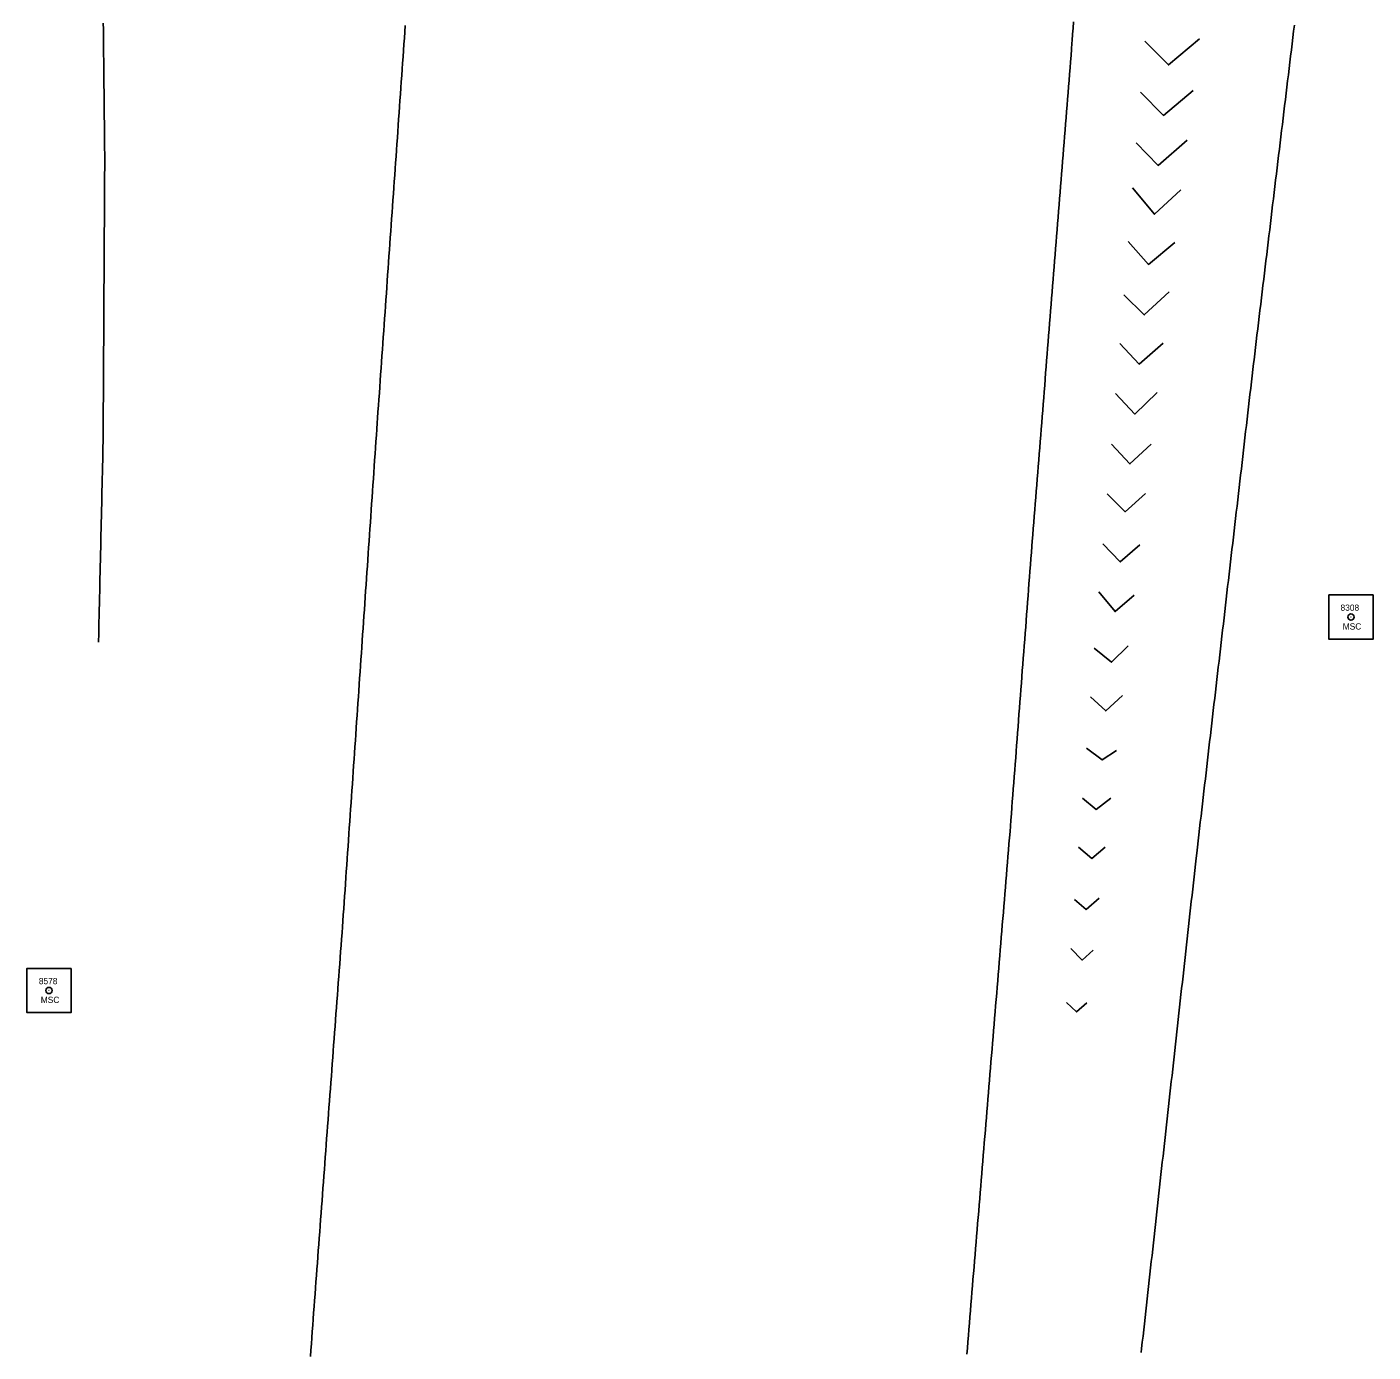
# Model space of a CAD drawing. Extents: x 205929 to 2357175, y -1785700 to 846739.
# Drawn here: x 2023502.7 to 2023718.1, y 811186.8 to 811398.9 of the extents above; entities that cross this region are included whole.
import ezdxf

# ---------------------------------------------------------------- set-up
doc = ezdxf.new("R2010")
doc.units = 0
for name, color, linetype in [('RD_HC_Survey', 7, 'Continuous'), ('RD_HC_txCode', 7, 'Continuous'), ('RD_Sketch1', 7, 'Continuous'), ('RD_SMD_Locator', 7, 'Continuous')]:
    doc.layers.add(name, color=color, linetype=linetype)

msp = doc.modelspace()

# ---------------------------------------------------------------- linework, layer by layer
at = {"layer": 'RD_HC_Survey'}
for points in [[(2023718.06, 811307.98), (2023710.99, 811307.98), (2023710.99, 811300.91), (2023718.06, 811300.91)], [(2023509.78, 811248.22), (2023502.71, 811248.22), (2023502.71, 811241.15), (2023509.78, 811241.15)]]:
    msp.add_lwpolyline(points, close=True, dxfattribs=at)
for centre in [(2023714.53, 811304.45), (2023506.25, 811244.69)]:
    msp.add_circle(centre, 0.5, dxfattribs=at)
at = {"layer": 'RD_Sketch1'}
for points in [[(2023514.93, 811399.5), (2023514.94, 811398.5), (2023514.95, 811397.5), (2023514.96, 811396.5), (2023514.97, 811395.5), (2023514.98, 811394.5), (2023514.99, 811393.5), (2023515, 811392.5), (2023515.01, 811391.5), (2023515.03, 811390.5), (2023515.04, 811389.5), (2023515.05, 811388.5), (2023515.06, 811387.5), (2023515.07, 811386.5), (2023515.08, 811385.5), (2023515.09, 811384.5), (2023515.1, 811383.5), (2023515.11, 811382.5), (2023515.12, 811381.5), (2023515.13, 811380.5), (2023515.14, 811379.5), (2023515.16, 811378.51), (2023515.16, 811378.29), (2023515.15, 811377.29), (2023515.15, 811376.29), (2023515.14, 811375.29), (2023515.14, 811374.29), (2023515.13, 811373.29), (2023515.12, 811372.29), (2023515.12, 811371.3), (2023515.11, 811370.3), (2023515.11, 811369.3), (2023515.1, 811368.3), (2023515.1, 811367.3), (2023515.09, 811366.3), (2023515.08, 811365.3), (2023515.08, 811364.3), (2023515.07, 811363.3), (2023515.07, 811362.3), (2023515.06, 811361.3), (2023515.06, 811360.3), (2023515.05, 811359.3), (2023515.05, 811358.3), (2023515.04, 811357.3), (2023515.03, 811356.3), (2023515.03, 811355.31), (2023515.02, 811354.31), (2023515.02, 811353.31), (2023515.01, 811352.31), (2023515.01, 811351.31), (2023515, 811350.31), (2023514.99, 811349.31), (2023514.99, 811348.31), (2023514.98, 811347.31), (2023514.98, 811346.31), (2023514.97, 811345.31), (2023514.97, 811344.31), (2023514.96, 811343.31), (2023514.96, 811342.31), (2023514.95, 811341.31), (2023514.94, 811340.31), (2023514.94, 811339.32), (2023514.93, 811338.32), (2023514.93, 811337.32), (2023514.92, 811336.32), (2023514.92, 811335.32), (2023514.91, 811334.32), (2023514.9, 811333.32), (2023514.9, 811332.59), (2023514.88, 811331.59), (2023514.85, 811330.59), (2023514.83, 811329.6), (2023514.81, 811328.6), (2023514.79, 811327.6), (2023514.76, 811326.6), (2023514.74, 811325.6), (2023514.72, 811324.6), (2023514.69, 811323.6), (2023514.67, 811322.6), (2023514.65, 811321.6), (2023514.62, 811320.6), (2023514.6, 811319.6), (2023514.58, 811318.6), (2023514.56, 811317.6), (2023514.53, 811316.6), (2023514.51, 811315.61), (2023514.49, 811314.61), (2023514.46, 811313.61), (2023514.44, 811312.61), (2023514.42, 811311.61), (2023514.39, 811310.61), (2023514.37, 811309.61), (2023514.35, 811308.61), (2023514.33, 811307.61), (2023514.3, 811306.61), (2023514.28, 811305.61), (2023514.26, 811304.61), (2023514.23, 811303.61), (2023514.21, 811302.61), (2023514.19, 811301.62), (2023514.16, 811300.62), (2023514.16, 811300.44)], [(2023563.24, 811399.1), (2023563.17, 811398.1), (2023563.1, 811397.1), (2023563.03, 811396.11), (2023562.96, 811395.11), (2023562.89, 811394.11), (2023562.81, 811393.11), (2023562.74, 811392.12), (2023562.67, 811391.12), (2023562.6, 811390.12), (2023562.53, 811389.13), (2023562.46, 811388.13), (2023562.39, 811387.13), (2023562.32, 811386.14), (2023562.25, 811385.14), (2023562.18, 811384.14), (2023562.11, 811383.14), (2023562.04, 811382.15), (2023561.97, 811381.15), (2023561.9, 811380.15), (2023561.83, 811379.16), (2023561.76, 811378.16), (2023561.69, 811377.16), (2023561.62, 811376.16), (2023561.55, 811375.17), (2023561.48, 811374.17), (2023561.41, 811373.17), (2023561.34, 811372.18), (2023561.27, 811371.18), (2023561.2, 811370.18), (2023561.13, 811369.18), (2023561.06, 811368.19), (2023560.99, 811367.19), (2023560.91, 811366.19), (2023560.84, 811365.2), (2023560.77, 811364.2), (2023560.7, 811363.2), (2023560.63, 811362.21), (2023560.56, 811361.21), (2023560.49, 811360.21), (2023560.42, 811359.21), (2023560.35, 811358.22), (2023560.28, 811357.22), (2023560.21, 811356.22), (2023560.14, 811355.23), (2023560.07, 811354.23), (2023560, 811353.23), (2023559.93, 811352.23), (2023559.86, 811351.24), (2023559.79, 811350.24), (2023559.72, 811349.24), (2023559.65, 811348.25), (2023559.58, 811347.25), (2023559.51, 811346.25), (2023559.44, 811345.25), (2023559.37, 811344.26), (2023559.3, 811343.26), (2023559.23, 811342.26), (2023559.16, 811341.27), (2023559.09, 811340.27), (2023559.01, 811339.27), (2023558.94, 811338.28), (2023558.87, 811337.28), (2023558.8, 811336.28), (2023558.75, 811335.54), (2023558.68, 811334.54), (2023558.61, 811333.55), (2023558.55, 811332.55), (2023558.48, 811331.55), (2023558.41, 811330.55), (2023558.34, 811329.56), (2023558.27, 811328.56), (2023558.2, 811327.56), (2023558.13, 811326.57), (2023558.06, 811325.57), (2023558, 811324.57), (2023557.93, 811323.58), (2023557.86, 811322.58), (2023557.79, 811321.58), (2023557.72, 811320.58), (2023557.65, 811319.59), (2023557.58, 811318.59), (2023557.51, 811317.59), (2023557.45, 811316.6), (2023557.38, 811315.6), (2023557.31, 811314.6), (2023557.24, 811313.6), (2023557.17, 811312.61), (2023557.1, 811311.61), (2023557.03, 811310.61), (2023556.96, 811309.62), (2023556.9, 811308.62), (2023556.83, 811307.62), (2023556.76, 811306.62), (2023556.69, 811305.63), (2023556.62, 811304.63), (2023556.55, 811303.63), (2023556.48, 811302.64), (2023556.41, 811301.64), (2023556.35, 811300.64), (2023556.28, 811299.64), (2023556.21, 811298.65), (2023556.14, 811297.65), (2023556.07, 811296.65), (2023556, 811295.66), (2023555.93, 811294.66), (2023555.86, 811293.66), (2023555.8, 811292.66), (2023555.73, 811291.67), (2023555.66, 811290.67), (2023555.59, 811289.67), (2023555.52, 811288.68), (2023555.45, 811287.68), (2023555.38, 811286.68), (2023555.32, 811285.68), (2023555.25, 811284.69), (2023555.18, 811283.69), (2023555.11, 811282.69), (2023555.04, 811281.7), (2023554.97, 811280.7), (2023554.9, 811279.7), (2023554.83, 811278.7), (2023554.77, 811277.71), (2023554.7, 811276.71), (2023554.63, 811275.71), (2023554.56, 811274.72), (2023554.49, 811273.72), (2023554.42, 811272.72), (2023554.35, 811271.72), (2023554.28, 811270.73), (2023554.22, 811269.73), (2023554.15, 811268.73), (2023554.08, 811267.74), (2023554.01, 811266.74), (2023553.94, 811265.74), (2023553.87, 811264.74), (2023553.8, 811263.75), (2023553.73, 811262.75), (2023553.67, 811261.75), (2023553.6, 811260.76), (2023553.53, 811259.76), (2023553.46, 811258.76), (2023553.39, 811257.76), (2023553.32, 811256.77), (2023553.25, 811255.77), (2023553.19, 811254.89), (2023553.12, 811253.89), (2023553.04, 811252.9), (2023552.97, 811251.9), (2023552.89, 811250.9), (2023552.82, 811249.91), (2023552.75, 811248.91), (2023552.67, 811247.91), (2023552.6, 811246.92), (2023552.52, 811245.92), (2023552.45, 811244.92), (2023552.37, 811243.93), (2023552.3, 811242.93), (2023552.23, 811241.93), (2023552.15, 811240.94), (2023552.08, 811239.94), (2023552, 811238.94), (2023551.93, 811237.95), (2023551.85, 811236.95), (2023551.78, 811235.95), (2023551.7, 811234.95), (2023551.63, 811233.96), (2023551.56, 811232.96), (2023551.48, 811231.96), (2023551.41, 811230.97), (2023551.33, 811229.97), (2023551.26, 811228.97), (2023551.18, 811227.98), (2023551.11, 811226.98), (2023551.03, 811225.98), (2023550.96, 811224.99), (2023550.89, 811223.99), (2023550.81, 811222.99), (2023550.74, 811222), (2023550.66, 811221), (2023550.59, 811220), (2023550.51, 811219.01), (2023550.44, 811218.01), (2023550.36, 811217.01), (2023550.29, 811216.02), (2023550.22, 811215.02), (2023550.14, 811214.02), (2023550.07, 811213.03), (2023549.99, 811212.03), (2023549.92, 811211.03), (2023549.84, 811210.04), (2023549.77, 811209.04), (2023549.7, 811208.04), (2023549.62, 811207.04), (2023549.55, 811206.05), (2023549.47, 811205.05), (2023549.4, 811204.05), (2023549.32, 811203.06), (2023549.25, 811202.06), (2023549.17, 811201.06), (2023549.1, 811200.07), (2023549.03, 811199.07), (2023548.95, 811198.07), (2023548.88, 811197.08), (2023548.8, 811196.08), (2023548.73, 811195.08), (2023548.65, 811194.09), (2023548.58, 811193.09), (2023548.5, 811192.09), (2023548.43, 811191.1), (2023548.36, 811190.1), (2023548.28, 811189.1), (2023548.21, 811188.11), (2023548.13, 811187.11), (2023548.06, 811186.11)], [(2023670.16, 811399.7), (2023670.08, 811398.7), (2023670, 811397.71), (2023669.92, 811396.71), (2023669.89, 811396.32), (2023669.82, 811395.32), (2023669.74, 811394.33), (2023669.66, 811393.33), (2023669.58, 811392.33), (2023669.5, 811391.34), (2023669.42, 811390.34), (2023669.34, 811389.34), (2023669.26, 811388.35), (2023669.18, 811387.35), (2023669.1, 811386.35), (2023669.02, 811385.36), (2023668.94, 811384.36), (2023668.86, 811383.37), (2023668.78, 811382.37), (2023668.7, 811381.37), (2023668.62, 811380.38), (2023668.54, 811379.38), (2023668.46, 811378.38), (2023668.39, 811377.39), (2023668.31, 811376.39), (2023668.23, 811375.39), (2023668.15, 811374.4), (2023668.07, 811373.4), (2023667.99, 811372.41), (2023667.91, 811371.41), (2023667.83, 811370.41), (2023667.75, 811369.42), (2023667.67, 811368.42), (2023667.59, 811367.42), (2023667.51, 811366.43), (2023667.43, 811365.43), (2023667.35, 811364.43), (2023667.27, 811363.44), (2023667.19, 811362.44), (2023667.11, 811361.45), (2023667.04, 811360.45), (2023666.96, 811359.45), (2023666.88, 811358.46), (2023666.8, 811357.46), (2023666.72, 811356.46), (2023666.64, 811355.47), (2023666.56, 811354.47), (2023666.48, 811353.47), (2023666.4, 811352.48), (2023666.32, 811351.48), (2023666.24, 811350.49), (2023666.16, 811349.49), (2023666.08, 811348.49), (2023666, 811347.5), (2023665.92, 811346.5), (2023665.84, 811345.5), (2023665.76, 811344.51), (2023665.68, 811343.51), (2023665.61, 811342.51), (2023665.53, 811341.52), (2023665.45, 811340.52), (2023665.37, 811339.53), (2023665.29, 811338.53), (2023665.21, 811337.53), (2023665.13, 811336.54), (2023665.05, 811335.54), (2023664.97, 811334.54), (2023664.89, 811333.55), (2023664.81, 811332.55), (2023664.73, 811331.55), (2023664.65, 811330.56), (2023664.57, 811329.56), (2023664.49, 811328.57), (2023664.41, 811327.57), (2023664.33, 811326.57), (2023664.26, 811325.58), (2023664.18, 811324.58), (2023664.1, 811323.58), (2023664.02, 811322.59), (2023663.94, 811321.59), (2023663.86, 811320.59), (2023663.78, 811319.6), (2023663.7, 811318.6), (2023663.62, 811317.61), (2023663.54, 811316.61), (2023663.48, 811315.8), (2023663.4, 811314.8), (2023663.32, 811313.81), (2023663.25, 811312.81), (2023663.17, 811311.81), (2023663.1, 811310.82), (2023663.02, 811309.82), (2023662.94, 811308.82), (2023662.87, 811307.83), (2023662.79, 811306.83), (2023662.71, 811305.84), (2023662.64, 811304.84), (2023662.56, 811303.84), (2023662.49, 811302.85), (2023662.41, 811301.85), (2023662.33, 811300.85), (2023662.26, 811299.86), (2023662.18, 811298.86), (2023662.11, 811297.86), (2023662.03, 811296.87), (2023661.95, 811295.87), (2023661.88, 811294.87), (2023661.8, 811293.88), (2023661.73, 811292.88), (2023661.65, 811291.88), (2023661.57, 811290.89), (2023661.5, 811289.89), (2023661.42, 811288.89), (2023661.34, 811287.9), (2023661.27, 811286.9), (2023661.19, 811285.9), (2023661.12, 811284.91), (2023661.04, 811283.91), (2023660.96, 811282.92), (2023660.89, 811281.92), (2023660.81, 811280.92), (2023660.74, 811279.93), (2023660.66, 811278.93), (2023660.58, 811277.93), (2023660.51, 811276.94), (2023660.43, 811275.94), (2023660.35, 811274.94), (2023660.28, 811273.95), (2023660.2, 811272.95), (2023660.13, 811271.95), (2023660.05, 811270.96), (2023659.99, 811270.14), (2023659.91, 811269.14), (2023659.82, 811268.15), (2023659.74, 811267.15), (2023659.66, 811266.15), (2023659.58, 811265.16), (2023659.49, 811264.16), (2023659.41, 811263.16), (2023659.33, 811262.17), (2023659.25, 811261.17), (2023659.17, 811260.18), (2023659.08, 811259.18), (2023659, 811258.18), (2023658.92, 811257.19), (2023658.84, 811256.19), (2023658.75, 811255.2), (2023658.67, 811254.2), (2023658.59, 811253.2), (2023658.51, 811252.21), (2023658.42, 811251.21), (2023658.34, 811250.21), (2023658.26, 811249.22), (2023658.18, 811248.22), (2023658.1, 811247.23), (2023658.01, 811246.23), (2023657.93, 811245.23), (2023657.85, 811244.24), (2023657.77, 811243.24), (2023657.68, 811242.25), (2023657.6, 811241.25), (2023657.52, 811240.25), (2023657.44, 811239.26), (2023657.35, 811238.26), (2023657.27, 811237.26), (2023657.19, 811236.27), (2023657.11, 811235.27), (2023657.03, 811234.28), (2023656.94, 811233.28), (2023656.86, 811232.28), (2023656.78, 811231.29), (2023656.7, 811230.29), (2023656.61, 811229.3), (2023656.53, 811228.3), (2023656.45, 811227.3), (2023656.37, 811226.31), (2023656.28, 811225.31), (2023656.2, 811224.31), (2023656.12, 811223.32), (2023656.04, 811222.32), (2023655.96, 811221.33), (2023655.87, 811220.33), (2023655.79, 811219.33), (2023655.71, 811218.34), (2023655.63, 811217.34), (2023655.54, 811216.35), (2023655.46, 811215.35), (2023655.38, 811214.35), (2023655.3, 811213.36), (2023655.22, 811212.36), (2023655.13, 811211.36), (2023655.05, 811210.37), (2023654.97, 811209.37), (2023654.89, 811208.38), (2023654.8, 811207.38), (2023654.72, 811206.38), (2023654.64, 811205.39), (2023654.56, 811204.39), (2023654.47, 811203.39), (2023654.39, 811202.4), (2023654.31, 811201.4), (2023654.23, 811200.41), (2023654.15, 811199.41), (2023654.06, 811198.41), (2023653.98, 811197.42), (2023653.9, 811196.42), (2023653.82, 811195.43), (2023653.73, 811194.43), (2023653.65, 811193.43), (2023653.57, 811192.44), (2023653.49, 811191.44), (2023653.4, 811190.44), (2023653.32, 811189.45), (2023653.24, 811188.45), (2023653.16, 811187.46), (2023653.08, 811186.46)], [(2023705.47, 811399.18), (2023705.35, 811398.19), (2023705.23, 811397.2), (2023705.11, 811396.21), (2023704.99, 811395.21), (2023704.87, 811394.22), (2023704.75, 811393.23), (2023704.63, 811392.24), (2023704.51, 811391.24), (2023704.39, 811390.25), (2023704.27, 811389.26), (2023704.15, 811388.27), (2023704.04, 811387.27), (2023703.92, 811386.28), (2023703.8, 811385.29), (2023703.68, 811384.3), (2023703.56, 811383.3), (2023703.44, 811382.31), (2023703.32, 811381.32), (2023703.2, 811380.33), (2023703.08, 811379.34), (2023702.96, 811378.34), (2023702.84, 811377.35), (2023702.72, 811376.36), (2023702.6, 811375.37), (2023702.48, 811374.37), (2023702.36, 811373.38), (2023702.24, 811372.39), (2023702.12, 811371.4), (2023702, 811370.4), (2023701.88, 811369.41), (2023701.76, 811368.42), (2023701.64, 811367.43), (2023701.53, 811366.43), (2023701.41, 811365.44), (2023701.29, 811364.45), (2023701.17, 811363.46), (2023701.05, 811362.47), (2023700.93, 811361.47), (2023700.81, 811360.48), (2023700.69, 811359.49), (2023700.57, 811358.5), (2023700.45, 811357.5), (2023700.33, 811356.51), (2023700.21, 811355.52), (2023700.09, 811354.53), (2023699.97, 811353.53), (2023699.85, 811352.54), (2023699.73, 811351.55), (2023699.61, 811350.56), (2023699.49, 811349.57), (2023699.37, 811348.57), (2023699.25, 811347.58), (2023699.13, 811346.59), (2023699.02, 811345.6), (2023698.95, 811345.05), (2023698.83, 811344.05), (2023698.72, 811343.06), (2023698.6, 811342.07), (2023698.49, 811341.08), (2023698.37, 811340.08), (2023698.26, 811339.09), (2023698.14, 811338.1), (2023698.03, 811337.11), (2023697.91, 811336.11), (2023697.8, 811335.12), (2023697.68, 811334.13), (2023697.57, 811333.14), (2023697.45, 811332.14), (2023697.34, 811331.15), (2023697.22, 811330.16), (2023697.11, 811329.17), (2023696.99, 811328.17), (2023696.87, 811327.18), (2023696.76, 811326.19), (2023696.64, 811325.2), (2023696.53, 811324.2), (2023696.41, 811323.21), (2023696.3, 811322.22), (2023696.18, 811321.23), (2023696.07, 811320.23), (2023695.95, 811319.24), (2023695.84, 811318.25), (2023695.72, 811317.26), (2023695.61, 811316.26), (2023695.49, 811315.27), (2023695.38, 811314.28), (2023695.26, 811313.29), (2023695.15, 811312.29), (2023695.03, 811311.3), (2023694.92, 811310.31), (2023694.8, 811309.32), (2023694.69, 811308.32), (2023694.57, 811307.33), (2023694.45, 811306.34), (2023694.34, 811305.35), (2023694.22, 811304.35), (2023694.11, 811303.36), (2023693.99, 811302.37), (2023693.88, 811301.38), (2023693.76, 811300.38), (2023693.65, 811299.39), (2023693.53, 811298.4), (2023693.42, 811297.41), (2023693.3, 811296.41), (2023693.19, 811295.42), (2023693.07, 811294.43), (2023692.96, 811293.44), (2023692.84, 811292.44), (2023692.73, 811291.45), (2023692.61, 811290.46), (2023692.5, 811289.47), (2023692.38, 811288.47), (2023692.27, 811287.48), (2023692.15, 811286.49), (2023692.03, 811285.5), (2023691.92, 811284.5), (2023691.8, 811283.51), (2023691.69, 811282.52), (2023691.57, 811281.53), (2023691.46, 811280.53), (2023691.34, 811279.54), (2023691.23, 811278.55), (2023691.11, 811277.56), (2023691, 811276.56), (2023690.88, 811275.57), (2023690.77, 811274.58), (2023690.65, 811273.59), (2023690.54, 811272.59), (2023690.42, 811271.6), (2023690.31, 811270.61), (2023690.19, 811269.62), (2023690.08, 811268.62), (2023689.96, 811267.63), (2023689.85, 811266.64), (2023689.76, 811265.88), (2023689.65, 811264.88), (2023689.54, 811263.89), (2023689.43, 811262.9), (2023689.32, 811261.9), (2023689.21, 811260.91), (2023689.1, 811259.92), (2023688.98, 811258.92), (2023688.87, 811257.93), (2023688.76, 811256.94), (2023688.65, 811255.94), (2023688.54, 811254.95), (2023688.43, 811253.96), (2023688.32, 811252.96), (2023688.21, 811251.97), (2023688.1, 811250.98), (2023687.99, 811249.98), (2023687.88, 811248.99), (2023687.77, 811247.99), (2023687.66, 811247), (2023687.55, 811246.01), (2023687.44, 811245.01), (2023687.33, 811244.02), (2023687.22, 811243.03), (2023687.11, 811242.03), (2023687, 811241.04), (2023686.89, 811240.05), (2023686.78, 811239.05), (2023686.67, 811238.06), (2023686.56, 811237.07), (2023686.45, 811236.07), (2023686.34, 811235.08), (2023686.23, 811234.08), (2023686.12, 811233.09), (2023686.01, 811232.1), (2023685.9, 811231.1), (2023685.79, 811230.11), (2023685.67, 811229.12), (2023685.56, 811228.12), (2023685.45, 811227.13), (2023685.34, 811226.14), (2023685.23, 811225.14), (2023685.12, 811224.15), (2023685.01, 811223.16), (2023684.9, 811222.16), (2023684.79, 811221.17), (2023684.68, 811220.18), (2023684.57, 811219.18), (2023684.46, 811218.19), (2023684.35, 811217.19), (2023684.24, 811216.2), (2023684.13, 811215.21), (2023684.02, 811214.21), (2023683.91, 811213.22), (2023683.8, 811212.23), (2023683.69, 811211.23), (2023683.58, 811210.24), (2023683.47, 811209.25), (2023683.36, 811208.25), (2023683.25, 811207.26), (2023683.14, 811206.27), (2023683.03, 811205.27), (2023682.92, 811204.28), (2023682.81, 811203.28), (2023682.7, 811202.29), (2023682.59, 811201.3), (2023682.48, 811200.3), (2023682.36, 811199.31), (2023682.25, 811198.32), (2023682.14, 811197.32), (2023682.03, 811196.33), (2023681.92, 811195.34), (2023681.81, 811194.34), (2023681.7, 811193.35), (2023681.59, 811192.36), (2023681.48, 811191.36), (2023681.37, 811190.37), (2023681.26, 811189.37), (2023681.15, 811188.38), (2023681.04, 811187.39), (2023680.97, 811186.75)], [(2023681.53, 811396.61), (2023685.32, 811392.81), (2023690.31, 811397.01)], [(2023680.86, 811388.44), (2023684.56, 811384.74), (2023689.29, 811388.73)], [(2023680.19, 811380.33), (2023683.7, 811376.72), (2023688.31, 811380.75)], [(2023679.6, 811373.12), (2023683.09, 811368.91), (2023687.33, 811372.84)], [(2023678.9, 811364.55), (2023682.16, 811360.89), (2023686.34, 811364.38)], [(2023678.2, 811356), (2023681.46, 811352.81), (2023685.42, 811356.52)], [(2023677.56, 811348.22), (2023680.65, 811344.94), (2023684.46, 811348.27)], [(2023676.88, 811340.22), (2023679.94, 811336.94), (2023683.55, 811340.41)], [(2023676.2, 811332.11), (2023679.17, 811328.97), (2023682.58, 811332.12)], [(2023675.53, 811324.16), (2023678.38, 811321.3), (2023681.66, 811324.2)], [(2023674.85, 811316.15), (2023677.61, 811313.27), (2023680.74, 811316)], [(2023674.2, 811308.48), (2023676.8, 811305.33), (2023679.82, 811307.95)], [(2023673.46, 811299.47), (2023676.2, 811297.22), (2023678.91, 811299.86)], [(2023672.85, 811291.69), (2023675.29, 811289.43), (2023678, 811291.87)], [(2023672.21, 811283.48), (2023674.71, 811281.59), (2023677, 811283.11)], [(2023671.58, 811275.46), (2023673.75, 811273.66), (2023676.11, 811275.45)], [(2023670.96, 811267.62), (2023673.07, 811265.82), (2023675.2, 811267.63)], [(2023670.31, 811259.24), (2023672.19, 811257.66), (2023674.25, 811259.47)], [(2023669.7, 811251.39), (2023671.53, 811249.54), (2023673.27, 811251.12)], [(2023669.04, 811242.78), (2023670.63, 811241.25), (2023672.28, 811242.73)]]:
    msp.add_lwpolyline(points, dxfattribs=at)
at = {"layer": 'RD_SMD_Locator'}
for centre in [(2023714.53, 811304.45), (2023506.25, 811244.69)]:
    msp.add_circle(centre, 0.001, dxfattribs=at)

# ---------------------------------------------------------------- texts
at = {"layer": 'RD_HC_txCode'}
for s, p in [('8308', (2023712.86, 811305.45)), ('MSC', (2023713.21, 811302.45)), ('8578', (2023504.62, 811245.69)), ('MSC', (2023504.93, 811242.69))]:
    msp.add_text(s, height=1, dxfattribs=at).set_placement(p)

doc.saveas('drawing.dxf')
